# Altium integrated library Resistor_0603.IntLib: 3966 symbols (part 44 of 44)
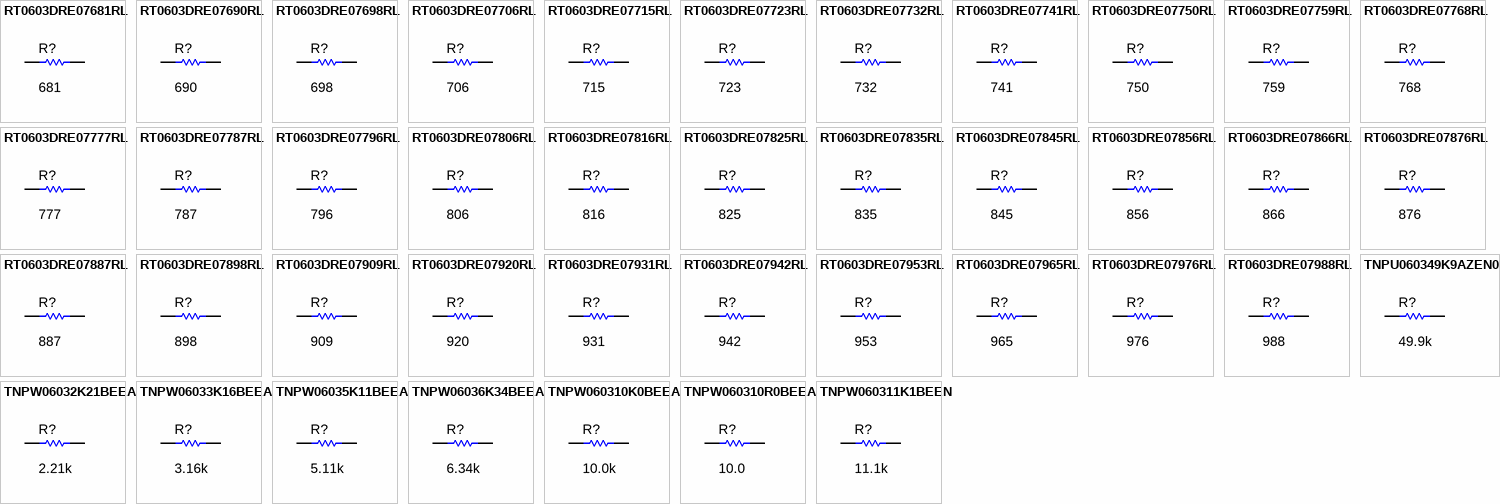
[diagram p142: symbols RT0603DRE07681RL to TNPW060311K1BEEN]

## RT0603DRE07787RL
designator R?  ValueDisplayed: 787  (hidden comment: RT0603DRE07787RL)
RES, 787, 0.5%, 0.1 W, 0603; Manufacturer: Yageo America; CompType: Resistor; Value: 787; Value_Code: 787R; Tolerance_%: 0.5; Power_W: 0.1; Value2: 0.1W; VDC_V: 75; TempCo: 50 ppm/C; SizeArea_mm2: 1.28; SizeX_mm: 1.6; SizeY_mm: 0.8; SizeZ_mm: 1; EIA_Code: E192; U/M: EA; AEC Category: Q200
signal-integrity model Resistor
simulation model Resistor
footprint 0603
footprint 0603M
footprint 0603L
footprint 0603_HV
footprint 0603S
pins: 1, 2

## RT0603DRE07796RL
designator R?  ValueDisplayed: 796  (hidden comment: RT0603DRE07796RL)
RES, 796, 0.5%, 0.1 W, 0603; Manufacturer: Yageo America; CompType: Resistor; Value: 796; Value_Code: 796R; Tolerance_%: 0.5; Power_W: 0.1; Value2: 0.1W; VDC_V: 75; TempCo: 50 ppm/C; SizeArea_mm2: 1.28; SizeX_mm: 1.6; SizeY_mm: 0.8; SizeZ_mm: 1; EIA_Code: E192; U/M: EA; AEC Category: Q200
signal-integrity model Resistor
simulation model Resistor
footprint 0603
footprint 0603M
footprint 0603L
footprint 0603_HV
footprint 0603S
pins: 1, 2

## RT0603DRE07806RL
designator R?  ValueDisplayed: 806  (hidden comment: RT0603DRE07806RL)
RES, 806, 0.5%, 0.1 W, 0603; Manufacturer: Yageo America; CompType: Resistor; Value: 806; Value_Code: 806R; Tolerance_%: 0.5; Power_W: 0.1; Value2: 0.1W; VDC_V: 75; TempCo: 50 ppm/C; SizeArea_mm2: 1.28; SizeX_mm: 1.6; SizeY_mm: 0.8; SizeZ_mm: 1; EIA_Code: E192; U/M: EA; AEC Category: Q200
signal-integrity model Resistor
simulation model Resistor
footprint 0603
footprint 0603M
footprint 0603L
footprint 0603_HV
footprint 0603S
pins: 1, 2

## RT0603DRE07816RL
designator R?  ValueDisplayed: 816  (hidden comment: RT0603DRE07816RL)
RES, 816, 0.5%, 0.1 W, 0603; Manufacturer: Yageo America; CompType: Resistor; Value: 816; Value_Code: 816R; Tolerance_%: 0.5; Power_W: 0.1; Value2: 0.1W; VDC_V: 75; TempCo: 50 ppm/C; SizeArea_mm2: 1.28; SizeX_mm: 1.6; SizeY_mm: 0.8; SizeZ_mm: 1; EIA_Code: E192; U/M: EA; AEC Category: Q200
signal-integrity model Resistor
simulation model Resistor
footprint 0603
footprint 0603M
footprint 0603L
footprint 0603_HV
footprint 0603S
pins: 1, 2

## RT0603DRE07825RL
designator R?  ValueDisplayed: 825  (hidden comment: RT0603DRE07825RL)
RES, 825, 0.5%, 0.1 W, 0603; Manufacturer: Yageo America; CompType: Resistor; Value: 825; Value_Code: 825R; Tolerance_%: 0.5; Power_W: 0.1; Value2: 0.1W; VDC_V: 75; TempCo: 50 ppm/C; SizeArea_mm2: 1.28; SizeX_mm: 1.6; SizeY_mm: 0.8; SizeZ_mm: 1; EIA_Code: E192; U/M: EA; AEC Category: Q200
signal-integrity model Resistor
simulation model Resistor
footprint 0603
footprint 0603M
footprint 0603L
footprint 0603_HV
footprint 0603S
pins: 1, 2

## RT0603DRE07835RL
designator R?  ValueDisplayed: 835  (hidden comment: RT0603DRE07835RL)
RES, 835, 0.5%, 0.1 W, 0603; Manufacturer: Yageo America; CompType: Resistor; Value: 835; Value_Code: 835R; Tolerance_%: 0.5; Power_W: 0.1; Value2: 0.1W; VDC_V: 75; TempCo: 50 ppm/C; SizeArea_mm2: 1.28; SizeX_mm: 1.6; SizeY_mm: 0.8; SizeZ_mm: 1; EIA_Code: E192; U/M: EA; AEC Category: Q200
signal-integrity model Resistor
simulation model Resistor
footprint 0603
footprint 0603M
footprint 0603L
footprint 0603_HV
footprint 0603S
pins: 1, 2

## RT0603DRE07845RL
designator R?  ValueDisplayed: 845  (hidden comment: RT0603DRE07845RL)
RES, 845, 0.5%, 0.1 W, 0603; Manufacturer: Yageo America; CompType: Resistor; Value: 845; Value_Code: 845R; Tolerance_%: 0.5; Power_W: 0.1; Value2: 0.1W; VDC_V: 75; TempCo: 50 ppm/C; SizeArea_mm2: 1.28; SizeX_mm: 1.6; SizeY_mm: 0.8; SizeZ_mm: 1; EIA_Code: E192; U/M: EA; AEC Category: Q200
signal-integrity model Resistor
simulation model Resistor
footprint 0603
footprint 0603M
footprint 0603L
footprint 0603_HV
footprint 0603S
pins: 1, 2

## RT0603DRE07856RL
designator R?  ValueDisplayed: 856  (hidden comment: RT0603DRE07856RL)
RES, 856, 0.5%, 0.1 W, 0603; Manufacturer: Yageo America; CompType: Resistor; Value: 856; Value_Code: 856R; Tolerance_%: 0.5; Power_W: 0.1; Value2: 0.1W; VDC_V: 75; TempCo: 50 ppm/C; SizeArea_mm2: 1.28; SizeX_mm: 1.6; SizeY_mm: 0.8; SizeZ_mm: 1; EIA_Code: E192; U/M: EA; AEC Category: Q200
signal-integrity model Resistor
simulation model Resistor
footprint 0603
footprint 0603M
footprint 0603L
footprint 0603_HV
footprint 0603S
pins: 1, 2

## RT0603DRE07866RL
designator R?  ValueDisplayed: 866  (hidden comment: RT0603DRE07866RL)
RES, 866, 0.5%, 0.1 W, 0603; Manufacturer: Yageo America; CompType: Resistor; Value: 866; Value_Code: 866R; Tolerance_%: 0.5; Power_W: 0.1; Value2: 0.1W; VDC_V: 75; TempCo: 50 ppm/C; SizeArea_mm2: 1.28; SizeX_mm: 1.6; SizeY_mm: 0.8; SizeZ_mm: 1; EIA_Code: E192; U/M: EA; AEC Category: Q200
signal-integrity model Resistor
simulation model Resistor
footprint 0603
footprint 0603M
footprint 0603L
footprint 0603_HV
footprint 0603S
pins: 1, 2

## RT0603DRE07876RL
designator R?  ValueDisplayed: 876  (hidden comment: RT0603DRE07876RL)
RES, 876, 0.5%, 0.1 W, 0603; Manufacturer: Yageo America; CompType: Resistor; Value: 876; Value_Code: 876R; Tolerance_%: 0.5; Power_W: 0.1; Value2: 0.1W; VDC_V: 75; TempCo: 50 ppm/C; SizeArea_mm2: 1.28; SizeX_mm: 1.6; SizeY_mm: 0.8; SizeZ_mm: 1; EIA_Code: E192; U/M: EA; AEC Category: Q200
signal-integrity model Resistor
simulation model Resistor
footprint 0603
footprint 0603M
footprint 0603L
footprint 0603_HV
footprint 0603S
pins: 1, 2

## RT0603DRE07887RL
designator R?  ValueDisplayed: 887  (hidden comment: RT0603DRE07887RL)
RES, 887, 0.5%, 0.1 W, 0603; Manufacturer: Yageo America; CompType: Resistor; Value: 887; Value_Code: 887R; Tolerance_%: 0.5; Power_W: 0.1; Value2: 0.1W; VDC_V: 75; TempCo: 50 ppm/C; SizeArea_mm2: 1.28; SizeX_mm: 1.6; SizeY_mm: 0.8; SizeZ_mm: 1; EIA_Code: E192; U/M: EA; AEC Category: Q200
signal-integrity model Resistor
simulation model Resistor
footprint 0603
footprint 0603M
footprint 0603L
footprint 0603_HV
footprint 0603S
pins: 1, 2

## RT0603DRE07898RL
designator R?  ValueDisplayed: 898  (hidden comment: RT0603DRE07898RL)
RES, 898, 0.5%, 0.1 W, 0603; Manufacturer: Yageo America; CompType: Resistor; Value: 898; Value_Code: 898R; Tolerance_%: 0.5; Power_W: 0.1; Value2: 0.1W; VDC_V: 75; TempCo: 50 ppm/C; SizeArea_mm2: 1.28; SizeX_mm: 1.6; SizeY_mm: 0.8; SizeZ_mm: 1; EIA_Code: E192; U/M: EA; AEC Category: Q200
signal-integrity model Resistor
simulation model Resistor
footprint 0603
footprint 0603M
footprint 0603L
footprint 0603_HV
footprint 0603S
pins: 1, 2

## RT0603DRE07909RL
designator R?  ValueDisplayed: 909  (hidden comment: RT0603DRE07909RL)
RES, 909, 0.5%, 0.1 W, 0603; Manufacturer: Yageo America; CompType: Resistor; Value: 909; Value_Code: 909R; Tolerance_%: 0.5; Power_W: 0.1; Value2: 0.1W; VDC_V: 75; TempCo: 50 ppm/C; SizeArea_mm2: 1.28; SizeX_mm: 1.6; SizeY_mm: 0.8; SizeZ_mm: 1; EIA_Code: E192; U/M: EA; AEC Category: Q200
signal-integrity model Resistor
simulation model Resistor
footprint 0603
footprint 0603M
footprint 0603L
footprint 0603_HV
footprint 0603S
pins: 1, 2

## RT0603DRE07920RL
designator R?  ValueDisplayed: 920  (hidden comment: RT0603DRE07920RL)
RES, 920, 0.5%, 0.1 W, 0603; Manufacturer: Yageo America; CompType: Resistor; Value: 920; Value_Code: 920R; Tolerance_%: 0.5; Power_W: 0.1; Value2: 0.1W; VDC_V: 75; TempCo: 50 ppm/C; SizeArea_mm2: 1.28; SizeX_mm: 1.6; SizeY_mm: 0.8; SizeZ_mm: 1; EIA_Code: E192; U/M: EA; AEC Category: Q200
signal-integrity model Resistor
simulation model Resistor
footprint 0603
footprint 0603M
footprint 0603L
footprint 0603_HV
footprint 0603S
pins: 1, 2

## RT0603DRE07931RL
designator R?  ValueDisplayed: 931  (hidden comment: RT0603DRE07931RL)
RES, 931, 0.5%, 0.1 W, 0603; Manufacturer: Yageo America; CompType: Resistor; Value: 931; Value_Code: 931R; Tolerance_%: 0.5; Power_W: 0.1; Value2: 0.1W; VDC_V: 75; TempCo: 50 ppm/C; SizeArea_mm2: 1.28; SizeX_mm: 1.6; SizeY_mm: 0.8; SizeZ_mm: 1; EIA_Code: E192; U/M: EA; AEC Category: Q200
signal-integrity model Resistor
simulation model Resistor
footprint 0603
footprint 0603M
footprint 0603L
footprint 0603_HV
footprint 0603S
pins: 1, 2

## RT0603DRE07942RL
designator R?  ValueDisplayed: 942  (hidden comment: RT0603DRE07942RL)
RES, 942, 0.5%, 0.1 W, 0603; Manufacturer: Yageo America; CompType: Resistor; Value: 942; Value_Code: 942R; Tolerance_%: 0.5; Power_W: 0.1; Value2: 0.1W; VDC_V: 75; TempCo: 50 ppm/C; SizeArea_mm2: 1.28; SizeX_mm: 1.6; SizeY_mm: 0.8; SizeZ_mm: 1; EIA_Code: E192; U/M: EA; AEC Category: Q200
signal-integrity model Resistor
simulation model Resistor
footprint 0603
footprint 0603M
footprint 0603L
footprint 0603_HV
footprint 0603S
pins: 1, 2

## RT0603DRE07953RL
designator R?  ValueDisplayed: 953  (hidden comment: RT0603DRE07953RL)
RES, 953, 0.5%, 0.1 W, 0603; Manufacturer: Yageo America; CompType: Resistor; Value: 953; Value_Code: 953R; Tolerance_%: 0.5; Power_W: 0.1; Value2: 0.1W; VDC_V: 75; TempCo: 50 ppm/C; SizeArea_mm2: 1.28; SizeX_mm: 1.6; SizeY_mm: 0.8; SizeZ_mm: 1; EIA_Code: E192; U/M: EA; AEC Category: Q200
signal-integrity model Resistor
simulation model Resistor
footprint 0603
footprint 0603M
footprint 0603L
footprint 0603_HV
footprint 0603S
pins: 1, 2

## RT0603DRE07965RL
designator R?  ValueDisplayed: 965  (hidden comment: RT0603DRE07965RL)
RES, 965, 0.5%, 0.1 W, 0603; Manufacturer: Yageo America; CompType: Resistor; Value: 965; Value_Code: 965R; Tolerance_%: 0.5; Power_W: 0.1; Value2: 0.1W; VDC_V: 75; TempCo: 50 ppm/C; SizeArea_mm2: 1.28; SizeX_mm: 1.6; SizeY_mm: 0.8; SizeZ_mm: 1; EIA_Code: E192; U/M: EA; AEC Category: Q200
signal-integrity model Resistor
simulation model Resistor
footprint 0603
footprint 0603M
footprint 0603L
footprint 0603_HV
footprint 0603S
pins: 1, 2

## RT0603DRE07976RL
designator R?  ValueDisplayed: 976  (hidden comment: RT0603DRE07976RL)
RES, 976, 0.5%, 0.1 W, 0603; Manufacturer: Yageo America; CompType: Resistor; Value: 976; Value_Code: 976R; Tolerance_%: 0.5; Power_W: 0.1; Value2: 0.1W; VDC_V: 75; TempCo: 50 ppm/C; SizeArea_mm2: 1.28; SizeX_mm: 1.6; SizeY_mm: 0.8; SizeZ_mm: 1; EIA_Code: E192; U/M: EA; AEC Category: Q200
signal-integrity model Resistor
simulation model Resistor
footprint 0603
footprint 0603M
footprint 0603L
footprint 0603_HV
footprint 0603S
pins: 1, 2

## RT0603DRE07988RL
designator R?  ValueDisplayed: 988  (hidden comment: RT0603DRE07988RL)
RES, 988, 0.5%, 0.1 W, 0603; Manufacturer: Yageo America; CompType: Resistor; Value: 988; Value_Code: 988R; Tolerance_%: 0.5; Power_W: 0.1; Value2: 0.1W; VDC_V: 75; TempCo: 50 ppm/C; SizeArea_mm2: 1.28; SizeX_mm: 1.6; SizeY_mm: 0.8; SizeZ_mm: 1; EIA_Code: E192; U/M: EA; AEC Category: Q200
signal-integrity model Resistor
simulation model Resistor
footprint 0603
footprint 0603M
footprint 0603L
footprint 0603_HV
footprint 0603S
pins: 1, 2

## TNPU060349K9AZEN00
designator R?  ValueDisplayed: 49.9k  (hidden comment: TNPU060349K9AZEN00)
RES, 49.9 k, 0.05%, 0.1 W, AEC-Q200 Grade 1, 0603; Manufacturer: Vishay-Dale; CompType: Resistor; Value: 49.9k; Res_ohm: 49900; Value_Code: 49k9; Tolerance_%: 0.05; Power_W: 0.1; Value2: 0.1W; VDC_V: 75; TempCo: 5 ppm/C; SizeArea_mm2: 1.28; SizeX_mm: 1.6; SizeY_mm: 0.8; SizeZ_mm: 1; U/M: EA; AEC Category: Q200; AEC Qualified: Y
signal-integrity model Resistor
simulation model Resistor
footprint 0603
footprint 0603M
footprint 0603L
footprint 0603_HV
footprint 0603S
pins: 1, 2

## TNPW06032K21BEEA
designator R?  ValueDisplayed: 2.21k  (hidden comment: TNPW06032K21BEEA)
RES, 2.21 k, 0.1%, 0.1 W, AEC-Q200 Grade 0, 0603; Manufacturer: Vishay-Dale; CompType: Resistor; Value: 2.21k; Res_ohm: 2210; Value_Code: 2k21; Tolerance_%: 0.1; Value2: 0.1W; VDC_V: 75; TempCo: 25 ppm/C; SizeArea_mm2: 1.36; SizeX_mm: 1.6; SizeY_mm: 0.85; SizeZ_mm: 0.55; EIA_Code: E192; U/M: EA; AEC Category: Q200; AEC Qualified: Y; AEC Grade: 0; Green_Lifecycle: Active; Green_REACh: Passed
signal-integrity model Resistor
simulation model Resistor
footprint TNPW0603
pins: 1, 2

## TNPW06033K16BEEA
designator R?  ValueDisplayed: 3.16k  (hidden comment: TNPW06033K16BEEA)
RES, 3.16 k, 0.1%, 0.1 W, AEC-Q200 Grade 1, 0603; Manufacturer: Vishay-Dale; CompType: Resistor; Value: 3.16k; Res_ohm: 3160; Value_Code: 3k16; Tolerance_%: 0.1; Value2: 0.1W; VDC_V: 75; TempCo: 25 ppm/C; SizeArea_mm2: 1.36; SizeX_mm: 1.6; SizeY_mm: 0.85; SizeZ_mm: 0.55; EIA_Code: E192; U/M: EA; AEC Category: Q200; AEC Qualified: Y; AEC Grade: 1
signal-integrity model Resistor
simulation model Resistor
footprint TNPW0603
pins: 1, 2

## TNPW06035K11BEEA
designator R?  ValueDisplayed: 5.11k  (hidden comment: TNPW06035K11BEEA)
RES, 5.11 k, 0.1%, 0.1 W, AEC-Q200 Grade 1, 0603; Manufacturer: Vishay-Dale; CompType: Resistor; Value: 5.11k; Res_ohm: 5110; Value_Code: 5k11; Tolerance_%: 0.1; Value2: 0.1W; VDC_V: 75; TempCo: 25 ppm/C; SizeArea_mm2: 1.36; SizeX_mm: 1.6; SizeY_mm: 0.85; SizeZ_mm: 0.55; EIA_Code: E192; U/M: EA; AEC Category: Q200; AEC Qualified: Y; AEC Grade: 1
signal-integrity model Resistor
simulation model Resistor
footprint TNPW0603
pins: 1, 2

## TNPW06036K34BEEA
designator R?  ValueDisplayed: 6.34k  (hidden comment: TNPW06036K34BEEA)
RES, 6.34 k, 0.1%, 0.1 W, AEC-Q200 Grade 1, 0603; Manufacturer: Vishay-Dale; CompType: Resistor; Value: 6.34k; Res_ohm: 6340; Value_Code: 6k34; Tolerance_%: 0.1; Value2: 0.1W; VDC_V: 75; TempCo: 25 ppm/C; SizeArea_mm2: 1.36; SizeX_mm: 1.6; SizeY_mm: 0.85; SizeZ_mm: 0.55; EIA_Code: E192; U/M: EA; AEC Category: Q200; AEC Qualified: Y; AEC Grade: 1
signal-integrity model Resistor
simulation model Resistor
footprint TNPW0603
pins: 1, 2

## TNPW060310K0BEEA
designator R?  ValueDisplayed: 10.0k  (hidden comment: TNPW060310K0BEEA)
RES, 10.0 k, 0.1%, 0.1 W, AEC-Q200 Grade 1, 0603; Manufacturer: Vishay-Dale; CompType: Resistor; Value: 10.0k; Res_ohm: 10000; Value_Code: 10k0; Tolerance_%: 0.1; Value2: 0.1W; VDC_V: 75; TempCo: 25 ppm/C; SizeArea_mm2: 1.36; SizeX_mm: 1.6; SizeY_mm: 0.85; SizeZ_mm: 0.55; EIA_Code: E192; U/M: EA; AEC Category: Q200; AEC Qualified: Y; AEC Grade: 1
signal-integrity model Resistor
simulation model Resistor
footprint TNPW0603
pins: 1, 2

## TNPW060310R0BEEA
designator R?  ValueDisplayed: 10.0  (hidden comment: TNPW060310R0BEEA)
RES, 10.0, 0.1%, 0.1 W, 0603; Manufacturer: Vishay-Dale; CompType: Resistor; Value: 10.0; Res_ohm: 10; Value_Code: 10R0; Tolerance_%: 0.1; Value2: 0.1W; VDC_V: 75; TempCo: 25 ppm/C; SizeArea_mm2: 1.28; SizeX_mm: 1.6; SizeY_mm: 0.8; SizeZ_mm: 1; EIA_Code: E192; U/M: EA; AEC Category: Q200; Green_Lifecycle: Active; Green_REACh: Passed
signal-integrity model Resistor
simulation model Resistor
footprint 0603
footprint 0603M
footprint 0603L
footprint 0603_HV
footprint 0603S
pins: 1, 2

## TNPW060311K1BEEN
designator R?  ValueDisplayed: 11.1k  (hidden comment: TNPW060311K1BEEN)
RES, 11.1 k, 0.1%, 0.1 W, AEC-Q200 Grade 0, 0603; Manufacturer: Vishay-Dale; CompType: Resistor; Value: 11.1k; Res_ohm: 11100; Value_Code: 11k1; Tolerance_%: 0.1; Value2: 0.1W; VDC_V: 75; TempCo: 15 ppm/C; SizeArea_mm2: 1.36; SizeX_mm: 1.6; SizeY_mm: 0.85; SizeZ_mm: 0.55; EIA_Code: E192; U/M: EA; AEC Category: Q200; AEC Qualified: Y; AEC Grade: 0
signal-integrity model Resistor
simulation model Resistor
footprint TNPW0603
pins: 1, 2

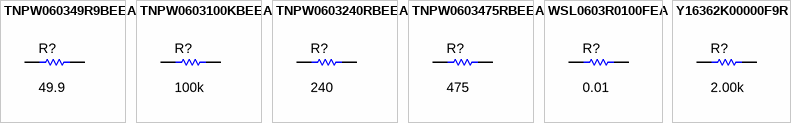
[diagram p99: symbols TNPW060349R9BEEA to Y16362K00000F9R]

## TNPW060349R9BEEA
designator R?  ValueDisplayed: 49.9  (hidden comment: TNPW060349R9BEEA)
RES, 49.9, 0.1%, 0.1 W, AEC-Q200 Grade 1, 0603; Manufacturer: Vishay-Dale; CompType: Resistor; Value: 49.9; Value_Code: 49R9; Tolerance_%: 0.1; Value2: 0.1W; VDC_V: 75; TempCo: 25 ppm/C; SizeArea_mm2: 1.36; SizeX_mm: 1.6; SizeY_mm: 0.85; SizeZ_mm: 0.55; EIA_Code: E192; U/M: EA; AEC Category: Q200; AEC Qualified: Y; AEC Grade: 1
signal-integrity model Resistor
simulation model Resistor
footprint TNPW0603
pins: 1, 2

## TNPW0603100KBEEA
designator R?  ValueDisplayed: 100k  (hidden comment: TNPW0603100KBEEA)
RES, 100 k, 0.1%, 0.1 W, AEC-Q200 Grade 1, 0603; Manufacturer: Vishay-Dale; CompType: Resistor; Value: 100k; Res_ohm: 100000; Tolerance_%: 0.1; Value2: 0.1W; VDC_V: 75; TempCo: 25 ppm/C; SizeArea_mm2: 1.28; SizeX_mm: 1.6; SizeY_mm: 0.8; SizeZ_mm: 1; EIA_Code: E192; U/M: EA; AEC Category: Q200; AEC Qualified: Y
signal-integrity model Resistor
simulation model Resistor
footprint 0603
footprint 0603M
footprint 0603L
footprint 0603_HV
footprint 0603S
pins: 1, 2

## TNPW0603240RBEEA
designator R?  ValueDisplayed: 240  (hidden comment: TNPW0603240RBEEA)
RES, 240, 0.1%, 0.1 W, AEC-Q200 Grade 1, 0603; Manufacturer: Vishay-Dale; CompType: Resistor; Value: 240; Value_Code: 240R; Tolerance_%: 0.1; Value2: 0.1W; VDC_V: 75; TempCo: 25 ppm/C; SizeArea_mm2: 1.36; SizeX_mm: 1.6; SizeY_mm: 0.85; SizeZ_mm: 0.55; EIA_Code: E192; U/M: EA; AEC Category: Q200; AEC Qualified: Y; AEC Grade: 1
signal-integrity model Resistor
simulation model Resistor
footprint TNPW0603
pins: 1, 2

## TNPW0603475RBEEA
designator R?  ValueDisplayed: 475  (hidden comment: TNPW0603475RBEEA)
RES, 475, 0.1%, 0.1 W, AEC-Q200 Grade 1, 0603; Manufacturer: Vishay-Dale; CompType: Resistor; Value: 475; Value_Code: 475R; Tolerance_%: 0.1; Value2: 0.1W; VDC_V: 75; TempCo: 25 ppm/C; SizeArea_mm2: 1.36; SizeX_mm: 1.6; SizeY_mm: 0.85; SizeZ_mm: 0.55; EIA_Code: E192; U/M: EA; AEC Category: Q200; AEC Qualified: Y; AEC Grade: 1
signal-integrity model Resistor
simulation model Resistor
footprint TNPW0603
pins: 1, 2

## WSL0603R0100FEA
designator R?  ValueDisplayed: 0.01  (hidden comment: WSL0603R0100FEA)
RES, 0.01, 1%, 0.1 W, 0603; Manufacturer: Vishay-Dale; CompType: Resistor; Value: 0.01; Value_Code: R010; Tolerance_%: 1; Power_W: 0.1; Value2: 0.1W; TempCo: 75 ppm/C; SizeArea_mm2: 1.1552; SizeX_mm: 1.52; SizeY_mm: 0.76; SizeZ_mm: 0.584; EIA_Code: E96; U/M: EA; AEC Category: Q200; AEC Qualified: N
signal-integrity model Resistor
simulation model Resistor
footprint WSL0603
pins: 1, 2

## Y16362K00000F9R
designator R?  ValueDisplayed: 2.00k  (hidden comment: Y16362K00000F9R)
RES, 2.00 k, 1%, 0.1 W, 0603; Manufacturer: Vishay Foil Resistors; CompType: Resistor; Value: 2.00k; Res_ohm: 2000; Value_Code: 2k00; Tolerance_%: 1; Power_W: 0.1; Value2: 0.1W; VDC_V: 20; TempCo: 0.2 ppm/C; SizeArea_mm2: 1.296; SizeX_mm: 1.6; SizeY_mm: 0.81; SizeZ_mm: 0.64; EIA_Code: E96; U/M: EA; AEC Category: Q200; AEC Qualified: N
signal-integrity model Resistor
simulation model Resistor
footprint VSMP_0603
pins: 1, 2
